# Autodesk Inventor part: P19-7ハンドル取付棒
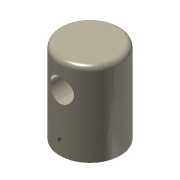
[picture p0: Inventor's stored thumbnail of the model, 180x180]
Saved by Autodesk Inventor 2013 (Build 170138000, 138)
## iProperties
Created: 2008-07
Part Number: P19-7ハンドル取付棒
Document SubType Name: Modeling
Designer: y-shimohigashi
Density: 1 g/cm^3
Stock Number: P19-7ハンドル取付棒
Material: 一般
Author: y-shimohigashi
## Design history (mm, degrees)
sketch "スケッチ1"
  geometry: C1 r 18 at (0, 0); 1 further point
  constraints: 1 centre point, 1 coincident
  dimensions: "d0" = 36 diameter of C1
extrude "押し出し1" new body sketch "スケッチ1" distance "d1" = 50; taper "d2" = 0 deg
sketch "スケッチ2"
  geometry: L1 (0, -10)-(0, 60) reference; L2 (-18, 50)-(18, 50) reference; C1 r 7 at (0, 34)
  constraints: 1 centre point, 1 point on line
  dimensions: "d3" = 14 diameter of C1; "d4" = 16 distance from line of L2 C1.centre
extrude "押し出し2" cut sketch "スケッチ2" stored distance "d5" = 50; taper "d6" = 0 deg
sketch "スケッチ3"
  geometry: L1 (0, -10)-(0, 60) reference; L2 (-18, 0)-(18, 0) reference; C1 r 1.5 at (0, 8)
  constraints: 1 centre point, 1 point on line
  dimensions: "d7" = 3 diameter of C1; "d8" = 8 distance from line of L2 C1.centre
extrude "押し出し3" cut sketch "スケッチ3" stored distance "d9" = 50; taper "d10" = 0 deg
feature "ねじ1" dims "d11" = 10, "d12" = 0
fillet "フィレット1" dims "d13" = 3
sketch "スケッチ4"
  geometry: L1 (3.536, -3.536)-(-3.536, -3.536); L2 (-3.536, -3.536)-(-3.536, 3.536); L3 (-3.536, 3.536)-(3.536, 3.536); L4 (3.536, 3.536)-(3.536, -3.536); L5 (3.536, 3.536)-(-3.536, -3.536); 2 further points
  constraints: 10 end point, 2 parallel, 2 perpendicular, 1 coincident, 1 horizontal, 1 midpoint
  dimensions: "d14" = 10 distance of L3.end L1.end
extrude "押し出し4" cut sketch "スケッチ4" stored distance "d15" = 50; taper "d16" = 0 deg
node "ソリッド1"
node "ソリッド ボディ"
node "サーフェス ボディ"
